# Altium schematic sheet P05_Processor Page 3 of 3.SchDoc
size 513 x 386 mm
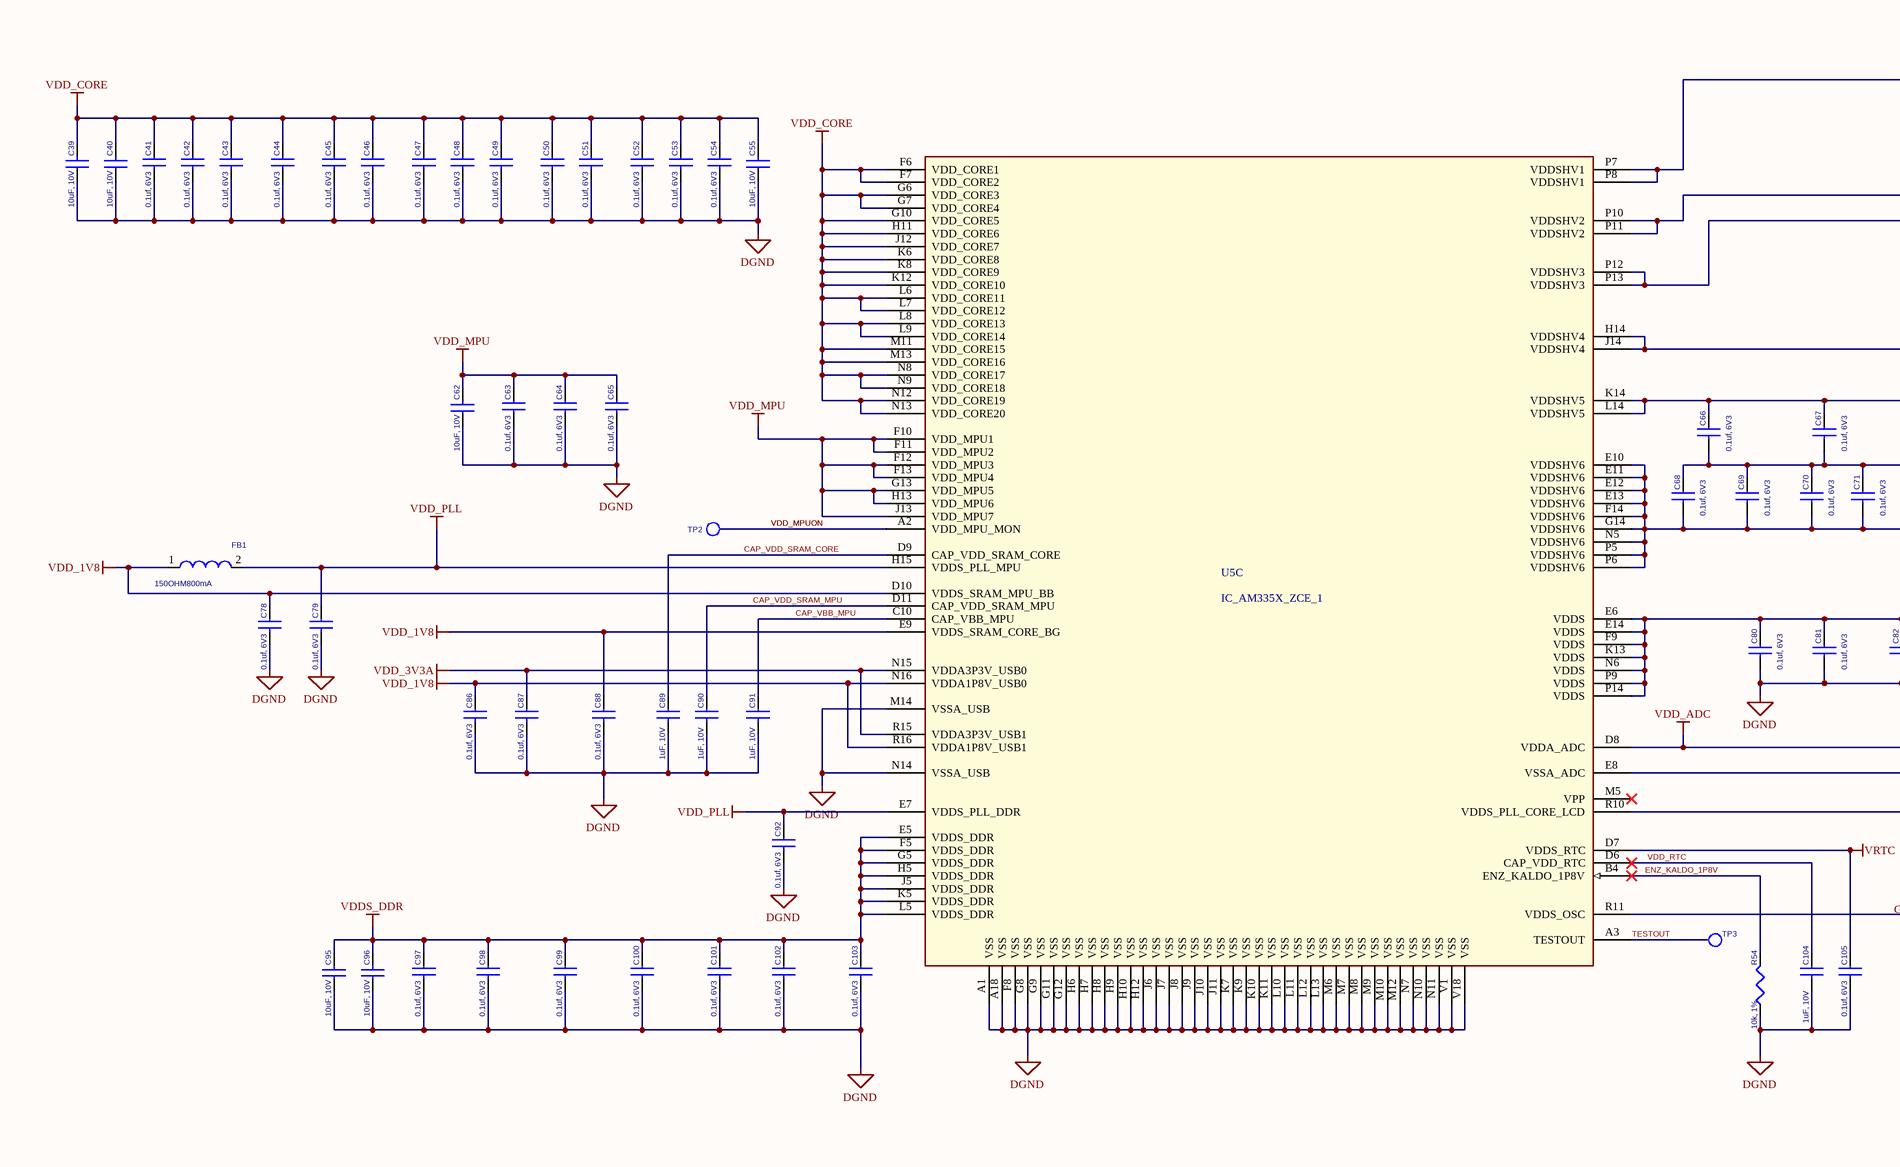
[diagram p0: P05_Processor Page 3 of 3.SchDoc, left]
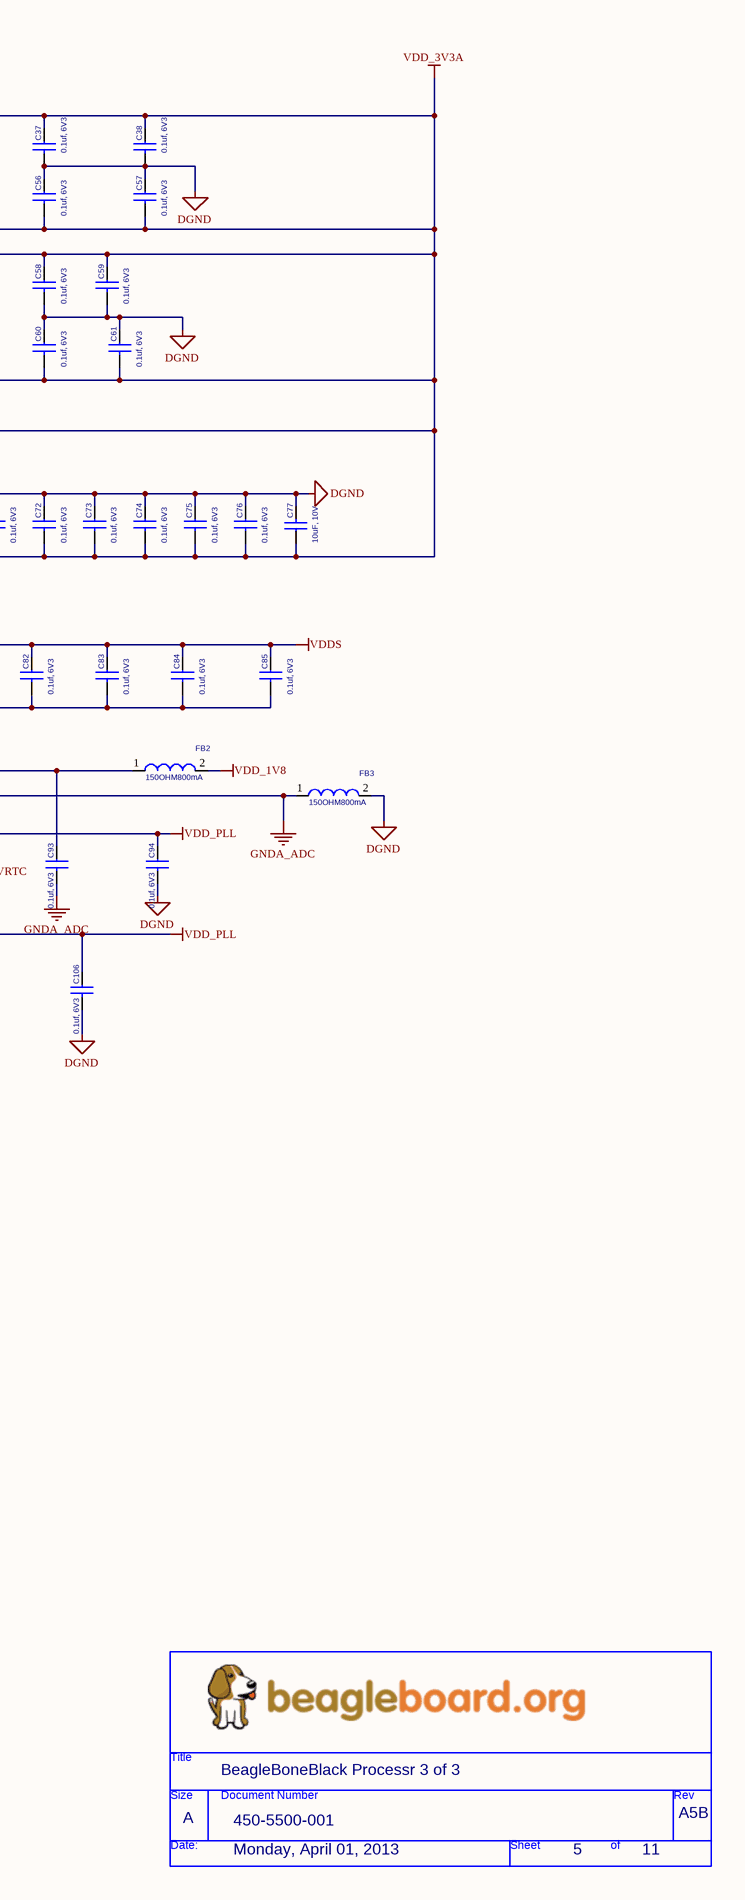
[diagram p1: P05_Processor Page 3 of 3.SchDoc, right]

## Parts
*  Page Create Date: Monday, April 01, 2013  Doc: 450-5500-001  RevCode: A5B  Title: BeagleBoneBlack Processr 3 of 3  Page Size: A  Page Number: 5  Page Count: 11  (hidden comment: BeagleBoard_org)  (graphical)
C37  0.1uf, 6V3  [402]
C38  0.1uf, 6V3  [402]
C39  10uF, 10V  [805]
C40  10uF, 10V  [805]
C41  0.1uf, 6V3  [402]
C42  0.1uf, 6V3  [402]
C43  0.1uf, 6V3  [402]
C44  0.1uf, 6V3  [402]
C45  0.1uf, 6V3  [402]
C46  0.1uf, 6V3  [402]
C47  0.1uf, 6V3  [402]
C48  0.1uf, 6V3  [402]
C49  0.1uf, 6V3  [402]
C50  0.1uf, 6V3  [402]
C51  0.1uf, 6V3  [402]
C52  0.1uf, 6V3  [402]
C53  0.1uf, 6V3  [402]
C54  0.1uf, 6V3  [402]
C55  10uF, 10V  [805]
C56  0.1uf, 6V3  [402]
C57  0.1uf, 6V3  [402]
C58  0.1uf, 6V3  [402]
C59  0.1uf, 6V3  [402]
C60  0.1uf, 6V3  [402]
C61  0.1uf, 6V3  [402]
C62  10uF, 10V  [805]
C63  0.1uf, 6V3  [402]
C64  0.1uf, 6V3  [402]
C65  0.1uf, 6V3  [402]
C66  0.1uf, 6V3  [402]
C67  0.1uf, 6V3  [402]
C68  0.1uf, 6V3  [402]
C69  0.1uf, 6V3  [402]
C70  0.1uf, 6V3  [402]
C71  0.1uf, 6V3  [402]
C72  0.1uf, 6V3  [402]
C73  0.1uf, 6V3  [402]
C74  0.1uf, 6V3  [402]
C75  0.1uf, 6V3  [402]
C76  0.1uf, 6V3  [402]
C77  10uF, 10V  [805]
C78  0.1uf, 6V3  [402]
C79  0.1uf, 6V3  [402]
C80  0.1uf, 6V3  [402]
C81  0.1uf, 6V3  [402]
C82  0.1uf, 6V3  [402]
C83  0.1uf, 6V3  [402]
C84  0.1uf, 6V3  [402]
C85  0.1uf, 6V3  [402]
C86  0.1uf, 6V3  [402]
C87  0.1uf, 6V3  [402]
C88  0.1uf, 6V3  [402]
C89  1uF, 10V  [402]
C90  1uF, 10V  [402]
C91  1uF, 10V  [402]
C92  0.1uf, 6V3  [402]
C93  0.1uf, 6V3  [402]
C94  0.1uf, 6V3  [402]
C95  10uF, 10V  [805]
C96  10uF, 10V  [805]
C97  0.1uf, 6V3  [402]
C98  0.1uf, 6V3  [402]
C99  0.1uf, 6V3  [402]
C100  0.1uf, 6V3  [402]
C101  0.1uf, 6V3  [402]
C102  0.1uf, 6V3  [402]
C103  0.1uf, 6V3  [402]
C104  1uF, 10V  [402]
C105  0.1uf, 6V3  [402]
C106  0.1uf, 6V3  [402]
FB1  150OHM800mA  [SM-7351-IND-0805]
FB2  150OHM800mA  [SM-7351-IND-0805]
FB3  150OHM800mA  [SM-7351-IND-0805]
R54  10k, 1%  [402]
TP2  TESTPT1  [TP60C_SMD]  (value not drawn)  (no BOM)
TP3  TESTPT1  [TP60C_SMD]  (value not drawn)  (no BOM)
U5  IC_AM335X_ZCE_1  [am33xx_15x15]  (part C of 3)

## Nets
DGND: C37.2 C38.2 C39.1 C40.1 C41.2 C42.2 C43.2 C44.2 C45.2 C46.2 C47.2 C48.2 C49.2 C50.2 C51.2 C52.2 C53.2 C54.2 C55.1 C56.1 C57.1 C58.2 C59.2 C60.1 C61.1 C62.1 C63.2 C64.2 C65.2 C66.2 C67.2 C68.1 C69.1 C70.1 C71.1 C72.1 C73.1 C74.1 C75.1 C76.1 C77.2 C78.2 C79.2 C80.2 C81.2 C82.2 C83.2 C84.2 C85.2 C86.2 C87.2 C88.2 C89.2 C90.2 C91.2 C92.2 C94.2 C95.1 C96.1 C97.2 C98.2 C99.2 C100.2 C101.2 C102.2 C103.2 C104.2 C105.2 C106.2 FB3.2 R54.1 U5.A1(VSS) U5.A18(VSS) U5.F8(VSS) U5.G8(VSS) U5.G9(VSS) U5.G11(VSS) U5.G12(VSS) U5.H6(VSS) U5.H7(VSS) U5.H8(VSS) U5.H9(VSS) U5.H10(VSS) U5.H12(VSS) U5.J6(VSS) U5.J7(VSS) U5.J8(VSS) U5.J9(VSS) U5.J10(VSS) U5.J11(VSS) U5.K7(VSS) U5.K9(VSS) U5.K10(VSS) U5.K11(VSS) U5.L10(VSS) U5.L11(VSS) U5.L12(VSS) U5.L13(VSS) U5.M6(VSS) U5.M7(VSS) U5.M8(VSS) U5.M9(VSS) U5.M10(VSS) U5.M12(VSS) U5.M14(VSSA_USB) U5.N7(VSS) U5.N10(VSS) U5.N11(VSS) U5.N14(VSSA_USB) U5.V1(VSS) U5.V18(VSS)
GNDA_ADC: C93.2 FB3.1 U5.E8(VSSA_ADC)
VDD_1V8: C78.1 C86.1 C88.1 FB1.1 FB2.2 U5.D10(VDDS_SRAM_MPU_BB) U5.E9(VDDS_SRAM_CORE_BG) U5.N16(VDDA1P8V_USB0) U5.R16(VDDA1P8V_USB1)
VDD_3V3A: C37.1 C38.1 C56.2 C57.2 C58.1 C59.1 C60.2 C61.2 C66.1 C67.1 C68.2 C69.2 C70.2 C71.2 C72.2 C73.2 C74.2 C75.2 C76.2 C77.1 C87.1 U5.E10(VDDSHV6) U5.E11(VDDSHV6) U5.E12(VDDSHV6) U5.E13(VDDSHV6) U5.F14(VDDSHV6) U5.G14(VDDSHV6) U5.H14(VDDSHV4) U5.J14(VDDSHV4) U5.K14(VDDSHV5) U5.L14(VDDSHV5) U5.N5(VDDSHV6) U5.N15(VDDA3P3V_USB0) U5.P5(VDDSHV6) U5.P6(VDDSHV6) U5.P7(VDDSHV1) U5.P8(VDDSHV1) U5.P10(VDDSHV2) U5.P11(VDDSHV2) U5.P12(VDDSHV3) U5.P13(VDDSHV3) U5.R15(VDDA3P3V_USB1)
VDD_ADC: C93.1 FB2.1 U5.D8(VDDA_ADC)
VDD_CORE: C39.2 C40.2 C41.1 C42.1 C43.1 C44.1 C45.1 C46.1 C47.1 C48.1 C49.1 C50.1 C51.1 C52.1 C53.1 C54.1 C55.2 U5.F6(VDD_CORE1) U5.F7(VDD_CORE2) U5.G6(VDD_CORE3) U5.G7(VDD_CORE4) U5.G10(VDD_CORE5) U5.H11(VDD_CORE6) U5.J12(VDD_CORE7) U5.K6(VDD_CORE8) U5.K8(VDD_CORE9) U5.K12(VDD_CORE10) U5.L6(VDD_CORE11) U5.L7(VDD_CORE12) U5.L8(VDD_CORE13) U5.L9(VDD_CORE14) U5.M11(VDD_CORE15) U5.M13(VDD_CORE16) U5.N8(VDD_CORE17) U5.N9(VDD_CORE18) U5.N12(VDD_CORE19) U5.N13(VDD_CORE20)
VDD_MPU: C62.2 C63.1 C64.1 C65.1 U5.F10(VDD_MPU1) U5.F11(VDD_MPU2) U5.F12(VDD_MPU3) U5.F13(VDD_MPU4) U5.G13(VDD_MPU5) U5.H13(VDD_MPU6) U5.J13(VDD_MPU7)
VDD_PLL: C79.1 C92.1 C94.1 C106.1 FB1.2 U5.E7(VDDS_PLL_DDR) U5.H15(VDDS_PLL_MPU) U5.R10(VDDS_PLL_CORE_LCD) U5.R11(VDDS_OSC)
VDDS: C80.1 C81.1 C82.1 C83.1 C84.1 C85.1 U5.E6(VDDS) U5.E14(VDDS) U5.F9(VDDS) U5.K13(VDDS) U5.N6(VDDS) U5.P9(VDDS) U5.P14(VDDS)
VDDS_DDR: C95.2 C96.2 C97.1 C98.1 C99.1 C100.1 C101.1 C102.1 C103.1 U5.E5(VDDS_DDR) U5.F5(VDDS_DDR) U5.G5(VDDS_DDR) U5.H5(VDDS_DDR) U5.J5(VDDS_DDR) U5.K5(VDDS_DDR) U5.L5(VDDS_DDR)
VRTC: C105.1 U5.D7(VDDS_RTC)
CAP_VBB_MPU: C91.1 U5.C10(CAP_VBB_MPU)
CAP_VDD_SRAM_CORE: C89.1 U5.D9(CAP_VDD_SRAM_CORE)
CAP_VDD_SRAM_MPU: C90.1 U5.D11(CAP_VDD_SRAM_MPU)
ENZ_KALDO_1P8V: R54.2 U5.B4(ENZ_KALDO_1P8V)
TESTOUT: TP3.1(TP) U5.A3(TESTOUT)
VDD_MPUON: TP2.1(TP) U5.A2(VDD_MPU_MON)
VDD_RTC: C104.1 U5.D6(CAP_VDD_RTC)

Not connected (* = marked no-connect by the designer): U5 M5(VPP)*

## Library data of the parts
C37 C38 C41-C54 C56-C61 C63-C76 C78-C88 C92-C94 C97-C103 C105 C106 = CAP_0.1uF_X7R_16V_10% 0402: CAP CER 0.1UF 6.3V 10% X5R 0402; Manufacturer: TDK Corporation; Manufacturer Part Number: C1005X5R0J104K050BA; Capacitance: 0.1µF
C39 C55 C62 C77 C95 C96 = CAP_10uF_Y5V_10V_10%_0805: CAP CER 10UF 10V Y5V 0805; Manufacturer: TDK Corporation; Manufacturer Part Number: C2012Y5V1A106Z; Capacitance: 10µF; Tolerance: -20%, +80%; Temperature Coefficient: Y5V (F)
C40 = CAP_10uF_Y5V_10V_10%_0805: CAP CER 10UF 10V Y5V 0805; Manufacturer: TDK Corporation; Manufacturer Part Number: C2012Y5V1A106Z; Capacitance: 10µF; Temperature Coefficient: Y5V (F); Tolerance: -20%, +80%
C89-C91 C104 = CAP_1.0UF_X5R_10V_10%_0402: CAP CER 1UF 10V 10% X5R 0402; Manufacturer: AVX Corporation; Manufacturer Part Number: 0402ZD105KAT2A; Capacitance: 1.0µF
FB1-FB3 = FER_180_200_0: FERRITE 800MA 150 OHM 0805 SMD; PartName: FerriteBead150ohm800mA; Mfr: Steward; MfrNum: LI0805H151R-10; TIIntPartnumber: 1L0010; Manufacturer: Laird-Signal Integrity Products; Vendor: Digikey; Impedance @ Frequency: 150 Ohm @ 100MHz; DC Resistance (DCR): 150 mOhm Max; Filter Type: Differential Mode - Single
R54 = RES_10K_1/16W_1%_0402: RES 10K OHM 1/16W 5% 0402 SMD; Manufacturer: Rohm Semiconductor; Manufacturer Part Number: MCR01MZPJ103; Power (Watts): 0.063W, 1/16W; Temperature Coefficient: ±200ppm/°C
U5 = IC_AM335X_ZCE_1: SubArctic Cortex A8 Processor 15x15; PartName: AM335X_15x15; Mfr: TI; MfrNum: AM335x 15x15 FBGA ZCE; TIIntPartnumber: 1A0242; Manufacturer: Texas Instruments; Manufacturer Part Number: XAM3359ZCZ; Vendor: Arrow; Cost100: 10.00; Processor Type: ARM Microprocessor; Voltage: 1.06 V ~ 1.15 V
